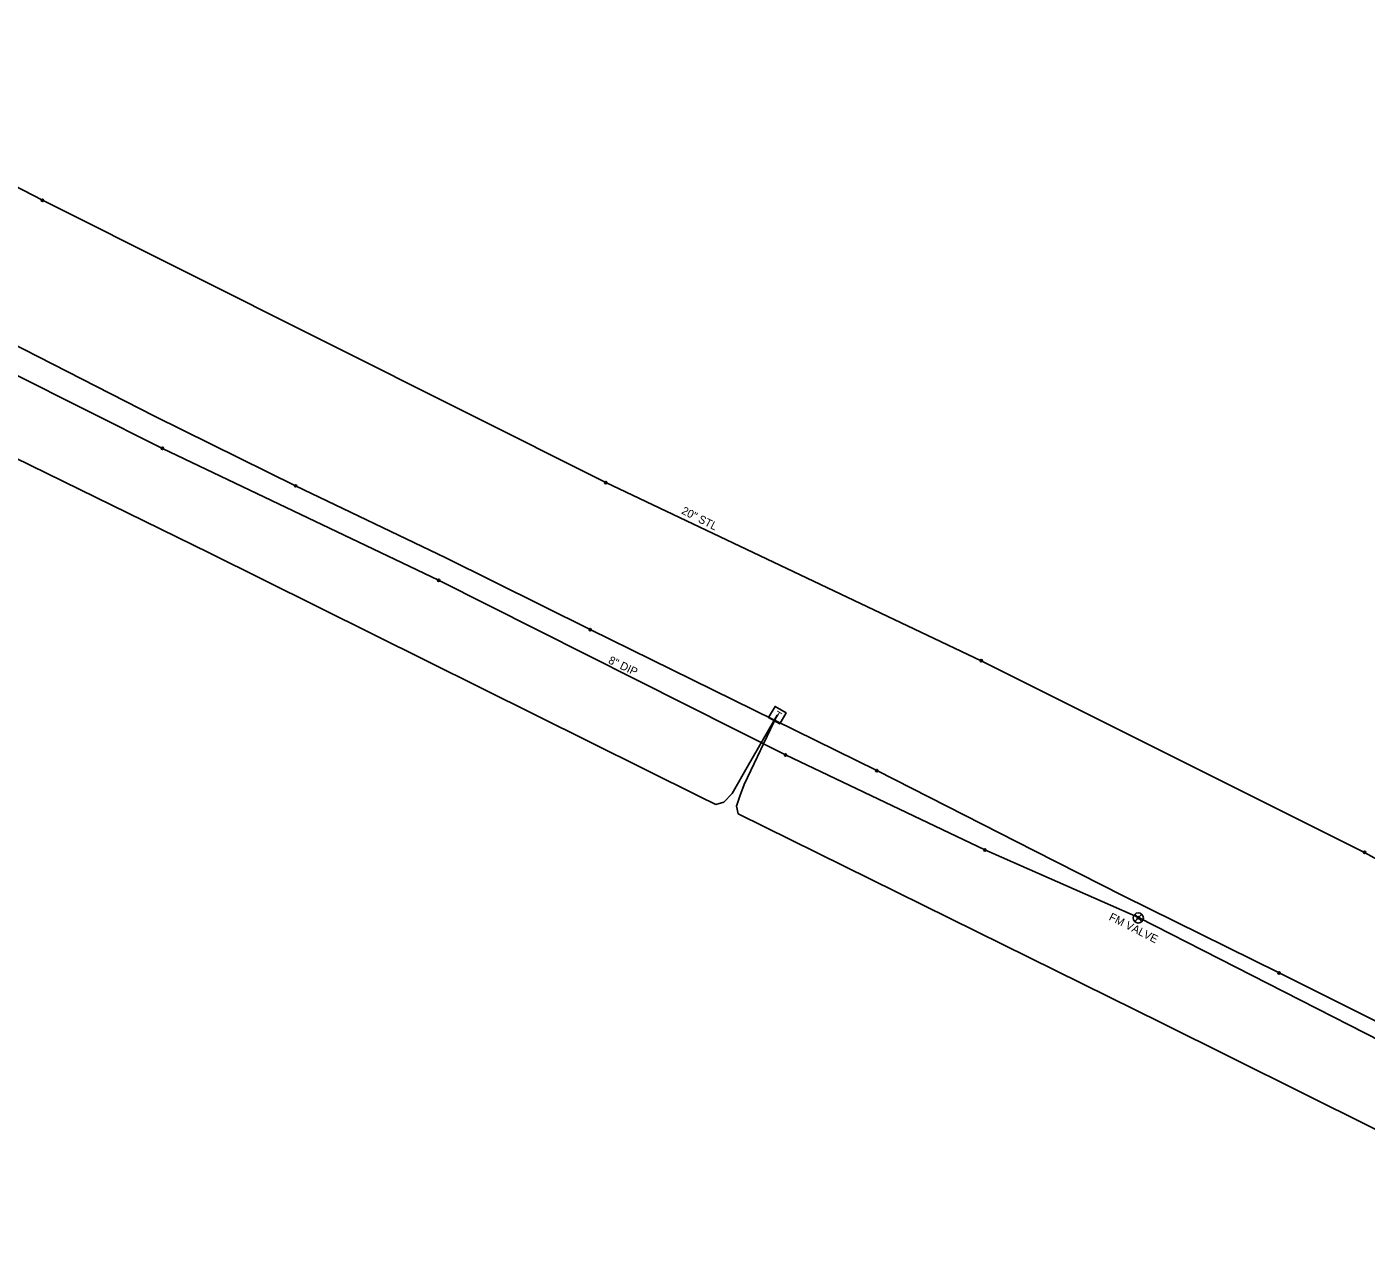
# Model space of a CAD drawing. Extents: x 2244485 to 2250986, y 199568 to 203007.
# Drawn here: x 2247742 to 2248328, y 200965 to 201502 of the extents above; entities that cross this region are included whole.
import ezdxf

# ---------------------------------------------------------------- set-up
doc = ezdxf.new("R2010")
doc.units = 0
for name, color, linetype in [('Default', 7, 'Continuous'), ('Exist Utilities Gas UG Line SUE LOS B', 7, 'Continuous'), ('Exist Utilities Gas UG Line SUE LOS B Text', 7, 'Continuous'), ('Exist Utilities Sanitary Sewer Forced Main SUE LOS B', 7, 'Continuous'), ('Exist Utilities Sanitary Sewer Forced Main SUE LOS B Text', 7, 'Continuous'), ('Exist Utilities Telephone Pedestal CELL', 7, 'Continuous'), ('Exist Utilities Telephone UG Cable SUE LOS C', 7, 'Continuous'), ('Exist Utilities Telephone UG FO SUE LOS B', 7, 'Continuous'), ('Exist Utilities Water Valve CELL', 7, 'Continuous')]:
    doc.layers.add(name, color=color, linetype=linetype)

# ---------------------------------------------------------------- blocks, each defined once
blk = doc.blocks.new('SurveyPointCell')
at = {"layer": 'Default'}
for p, q in [((-0.5, 0), (0.5, 0)), ((0, -0.5), (0, 0.5))]:
    blk.add_line(p, q, dxfattribs=at)
blk.add_circle((0, 0), 0.5, dxfattribs=at)

msp = doc.modelspace()

# ---------------------------------------------------------------- linework, layer by layer
at = {"layer": 'Exist Utilities Gas UG Line SUE LOS B'}
msp.add_lwpolyline([(2247602.4, 201501.88), (2247749.1, 201426.01), (2247995.53, 201302.57), (2248159.78, 201224.66), (2248327.53, 201140.85), (2248373.07, 201115.64), (2248475.56, 201067.34), (2248547.65, 201031.24), (2248651.39, 200979.65), (2248754.41, 200927.49), (2248898.77, 200854.93), (2249046.68, 200783.06), (2249166.77, 200725.47), (2249287.36, 200663.03), (2249402.68, 200604.16)], dxfattribs=at)
at = {"layer": 'Exist Utilities Sanitary Sewer Forced Main SUE LOS B'}
msp.add_lwpolyline([(2247735.41, 201350.67), (2247801.59, 201317.51), (2247922.39, 201259.82), (2248074.17, 201183.48), (2248161.38, 201141.9), (2248228.53, 201112.29), (2248334.87, 201058.12), (2248487.25, 200983.06), (2248649.22, 200895.6), (2248733.43, 200859.57), (2248875.85, 200789.39), (2249055.92, 200697.85), (2249217.76, 200621.23), (2249370.62, 200544.89)], dxfattribs=at)
at = {"layer": 'Exist Utilities Telephone Pedestal CELL'}
msp.add_line((2248070.58, 201200.89), (2248070.58, 201200.89), dxfattribs=at)
msp.add_lwpolyline([(2248066.8, 201199.83), (2248071.62, 201197), (2248074.46, 201201.82), (2248069.63, 201204.66), (2248066.8, 201199.83)], dxfattribs=at)
at = {"layer": 'Exist Utilities Telephone UG Cable SUE LOS C'}
msp.add_lwpolyline([(2247686.97, 201337.82), (2247821.99, 201271.82), (2248036.57, 201165.31), (2248043.75, 201161.81), (2248047.17, 201162.83), (2248050.78, 201166.64), (2248058.05, 201179.15), (2248070.58, 201200.89), (2248056.13, 201170.56), (2248054.15, 201165.45), (2248052.67, 201161.08), (2248053.42, 201157.76), (2248238.7, 201066.28), (2248423.59, 200974.24)], dxfattribs=at)
at = {"layer": 'Exist Utilities Telephone UG FO SUE LOS B'}
msp.add_lwpolyline([(2247734.6, 201364.13), (2247798.15, 201331.66), (2247859.88, 201301.14), (2247925.6, 201269.67), (2247988.72, 201238.28), (2248114.06, 201176.6), (2248183.16, 201141.53), (2248221.91, 201121.81), (2248290.07, 201088.12), (2248488.94, 200988.89), (2248609.32, 200928.77), (2248687.7, 200891.02), (2248748.44, 200861.37), (2248829.89, 200822.11), (2248864.68, 200804.04), (2248883.46, 200794.42), (2248944.92, 200764.27), (2249005.82, 200733.82), (2249066.5, 200704.1), (2249128.64, 200672.91), (2249190.46, 200641.51), (2249254.14, 200610.49), (2249321.49, 200578.44), (2249387.5, 200544.86)], dxfattribs=at)
at = {"layer": 'Exist Utilities Water Valve CELL'}
msp.add_lwpolyline([(2248230.08, 201113.74), (2248226.93, 201110.59), (2248228.5, 201112.16), (2248230.08, 201110.59), (2248226.93, 201113.74)], dxfattribs=at)
msp.add_circle((2248228.5, 201112.16), 2.23, dxfattribs=at)

# ---------------------------------------------------------------- block references
at = {"layer": 'Default'}
for p in [(2247749.1, 201426.01), (2247801.59, 201317.51), (2247859.88, 201301.14), (2247995.53, 201302.57), (2247922.39, 201259.82), (2247988.72, 201238.28), (2248159.78, 201224.66), (2248074.17, 201183.48), (2248114.06, 201176.6), (2248161.38, 201141.9), (2248327.53, 201140.85), (2248228.53, 201112.29), (2248290.07, 201088.12)]:
    msp.add_blockref('SurveyPointCell', p, dxfattribs=at)

# ---------------------------------------------------------------- texts
at = {"layer": 'Exist Utilities Gas UG Line SUE LOS B Text'}
msp.add_text('20" STL', height=3.5, rotation=333.09153, dxfattribs=at).set_placement((2248028.37, 201289.13))
at = {"layer": 'Exist Utilities Sanitary Sewer Forced Main SUE LOS B'}
msp.add_text('FM VALVE', height=3.5, rotation=333.09153, dxfattribs=at).set_placement((2248215.36, 201111.46))
at = {"layer": 'Exist Utilities Sanitary Sewer Forced Main SUE LOS B Text'}
msp.add_text('8" DIP', height=3.5, rotation=334.4319, dxfattribs=at).set_placement((2247996.37, 201223.7))
at = {"layer": 'Exist Utilities Telephone Pedestal CELL'}
msp.add_text('T', height=3.42, rotation=329.58504, dxfattribs=at).set_placement((2248068.74, 201199.98))

doc.saveas('drawing.dxf')
